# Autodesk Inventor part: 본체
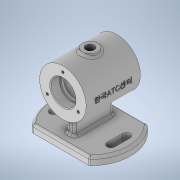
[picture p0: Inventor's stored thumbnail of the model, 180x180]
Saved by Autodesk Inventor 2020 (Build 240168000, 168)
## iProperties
Created: 2021-09
Part Number: 본체
Material: 일반
Document SubType Name: Modeling
Designer: Administrator
Density: 1 g/cm^3
Appearance: 기본값
Author: Administrator
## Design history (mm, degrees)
sketch "스케치1"
  geometry: L1 (-37.5, -62.928)-(37.5, -62.928); L2 (37.5, -62.928)-(37.5, 62.928); L3 (37.5, 62.928)-(-37.5, 62.928); L4 (-37.5, 62.928)-(-37.5, -62.928); L5 (-37.5, -62.928)-(37.5, 62.928); L6 (37.5, -62.928)-(-37.5, 62.928); C1 r 52.5 at (0, 0); 5 further points
  constraints: 12 end point, 2 midpoint, 2 parallel, 1 centre point, 1 coincident, 1 horizontal, 1 perpendicular
  dimensions: "d0" = 105 diameter of C1; "d1" = 75 distance of L2.end L3.end
extrude "돌출1" new body sketch "스케치1" distance "d2" = 10; taper "d3" = 0 deg
sketch "스케치2"
  geometry: L1 (36.742, 0)-(-36.742, 0) reference; C1 r 30 at (0, 62); 2 further points
  constraints: 1 centre point, 1 midpoint, 1 vertical alignment
  dimensions: "d4" = 62 distance from line of C1.centre L1; "d5" = 60 diameter of C1
extrude "돌출2" join sketch "스케치2" stored distance "d6" = 70; taper "d7" = 0 deg
node "작업 평면1"
sketch "스케치3"
  geometry: C1 r 10 at (0, 0); 1 further point
  constraints: 1 centre point, 1 coincident
  dimensions: "d9" = 20 diameter of C1
extrude "돌출3" join sketch "스케치3" stored distance "d10" = 70; taper "d11" = 0 deg
sketch "스케치4"
  geometry: L1 (25, 5.965)-(-25, 5.965); L2 (-25, 5.965)-(-25, 55.287); L3 (-25, 55.287)-(25, 55.287); L4 (25, 55.287)-(25, 5.965); L5 (25, 5.965)-(-25, 55.287); L6 (-25, 5.965)-(25, 55.287); 2 further points
  constraints: 12 end point, 2 midpoint, 2 parallel, 1 horizontal, 1 perpendicular
  dimensions: "d12" = 50 distance of L1.start L1.end
extrude "돌출4" join sketch "스케치4" stored distance "d13" = 10; taper "d14" = 0 deg
sketch "스케치5"
  geometry: L1 (35, 32)-(35, 92) reference; L2 (35, 62)-(-43.951, 62); L3 (-35, 92)-(-35, 32) reference; L4 (35, 78)-(23, 78); L5 (23, 78)-(23, 76); L6 (23, 76)-(20, 76); L7 (20, 76)-(20, 87); L8 (20, 87)-(-20, 87); L9 (-20, 87)-(-20, 76); L10 (-20, 76)-(-23, 76); L11 (-23, 76)-(-23, 78); L12 (-23, 78)-(-35, 78); 2 further points
  constraints: 20 end point, 6 perpendicular, 5 point on line, 3 horizontal, 1 midpoint
  dimensions: "d15" = 12 distance of L4.start L4.end; "d16" = 40 distance of L7.end L8.end; "d17" = 12 distance of L11.end L12.end; "d18" = 32 diameter of L4 L2; "d19" = 28 diameter of L6 L2; "d20" = 3 distance of L5.end L6.end; "d21" = 50 diameter of L8 L2
revolve "회전1" sketch "스케치5" stored, may be unused: angle "d22" = 90 deg
chamfer "모따기1" distance "d23" = 1; stored, may be unused: second distance "d24" = 2, angle "d25" = 45 deg
fillet "모깎기1" dims "d26" = 0.3
fillet "모깎기2" dims "d27" = 3
sketch "스케치6"
  geometry: C1 r 30 at (0, 0) reference; 2 further points
  constraints: 1 horizontal alignment
  dimensions: "d28" = 23 distance of point (-23, 0) C1.centre
hole "구멍1" sketch "스케치6" at (-23, 0) diameter "d29" = 3.242; stored, may be unused: countersink angle "d33" = 90 deg, drill point angle "d35" = 118 deg; dims "d30" = 8, "d31" = 4, "d32" = 2, "d34" = 10
sketch "스케치7"
  geometry: C1 r 10 at (0, 0) reference; 2 further points
  constraints: 1 coincident
hole "구멍2" sketch "스케치7" at (0, 0) diameter "d39" = 10.917; stored, may be unused: countersink angle "d43" = 90 deg, drill point angle "d45" = 118 deg; dims "d40" = 24, "d41" = 4, "d42" = 2, "d44" = 29.1
sketch "스케치8"
  geometry: L1 (-10, 37)-(10, 37); L2 (-10, 32)-(10, 32); L3 (10, 42)-(-10, 42); L4 (-10, -37)-(10, -37); L5 (-10, -42)-(10, -42); L6 (10, -32)-(-10, -32); A1 r 5 centre (-10, 37) between (-10, 42) and (-10, 32); A2 r 5 centre (10, 37) between (10, 32) and (10, 42); A3 r 5 centre (-10, -37) between (-10, -32) and (-10, -42); A4 r 5 centre (10, -37) between (10, -42) and (10, -32); 3 further points
  constraints: 16 end point, 8 point on circle, 8 tangent, 4 centre point, 3 parallel, 3 vertical alignment, 2 midpoint, 1 horizontal
  dimensions: "d46" = 20 distance of L1.end L1.start; "d47" = 5 radius of A1; "d48" = 5 radius of A3; "d49" = 37 vertical distance of point (0, 0) L1.start; "d50" = 37 vertical distance of L4.start point (0, 0)
extrude "돌출5" cut sketch "스케치8" extent not by distance; stored distance "d51" = 0; taper "d52" = 0 deg
node "작업 평면2"
sketch "스케치9"
  geometry: L1 (-35, 92)-(-35, 32) reference; 2 further points
  constraints: 1 other
  dimensions: "d54" = 35 distance from line of point (0, 62) L1; "d55" = 30 vertical distance of point (0, 62) L1.start
feature "엠보싱1" sketch "스케치9" dims "d0" = 105, "d1" = 75, "d56" = 0.5, "d57" = 0
fillet "모깎기3" dims "d58" = 3
fillet "모깎기4" dims "d59" = 3
node "솔리드1"
pattern_circular "원형 패턴1" dims angle "d37" = 360 deg
mirror "미러1"
feature "A9D066F2-1C7D-4E18-AEED-F7BC21143FA4" dims "d29" = 3.242, "d30" = 8, "d31" = 4, "d32" = 2, "d33" = 90 deg, "d34" = 10, "d35" = 118 deg
other parameters: "d8" = 95, "d53" = 77.75
